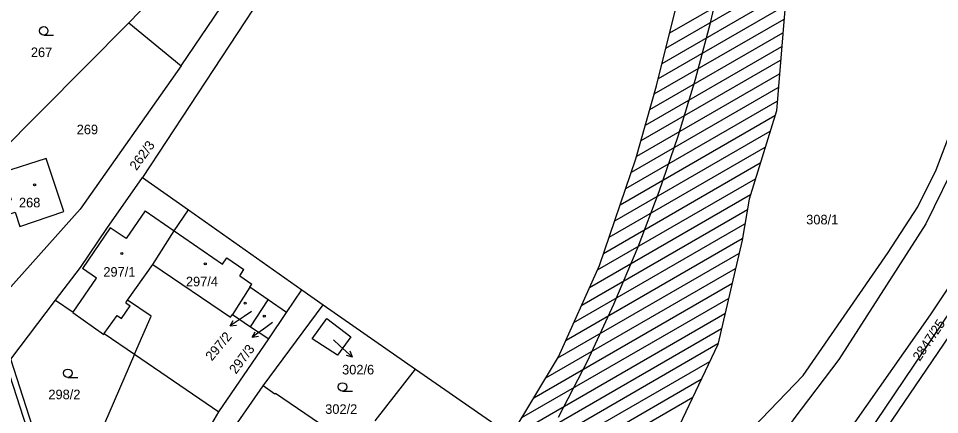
# Model space of a CAD drawing. Extents: x -558500 to -557517, y -1073973 to -1073051.
# Drawn here: x -558169.6 to -558006.2, y -1073303.2 to -1073232.9 of the extents above; entities that cross this region are included whole.
import ezdxf

# ---------------------------------------------------------------- set-up
doc = ezdxf.new("R2010")
doc.units = 0
for name, color, linetype in [('Hranice parcel', 7, 'Continuous'), ('Kolej', 7, 'Continuous'), ('Parcelní čísla', 7, 'Continuous'), ('Pop  PČ popisy', 7, 'Continuous'), ('Svazek obcí údolí Desné', 7, 'Continuous'), ('Vnitřní kresba', 7, 'Continuous'), ('Značky budov', 7, 'Continuous'), ('Značky kultur', 7, 'Continuous')]:
    doc.layers.add(name, color=color, linetype=linetype)

msp = doc.modelspace()

# ---------------------------------------------------------------- linework, layer by layer
at = {"layer": 'Hranice parcel'}
for p, q in [((-558140.75, -1073241.36), (-558126.3, -1073220.06)), ((-558122.4, -1073222.85), (-558147.61, -1073261.18)), ((-558180.27, -1073264.19), (-558150.02, -1073233.76)), ((-558150.02, -1073233.76), (-558140.75, -1073241.36)), ((-558147.61, -1073261.18), (-558139.47, -1073266.91)), ((-558139.47, -1073266.91), (-558119.31, -1073281.1)), ((-557994.86, -1073270.9), (-558022.09, -1073311.21)), ((-558122.04, -1073285.13), (-558119.31, -1073281.1)), ((-558119.31, -1073281.1), (-558115.55, -1073283.75)), ((-558170.97, -1073293.42), (-558163.02, -1073282.94)), ((-558128.43, -1073287.66), (-558125.31, -1073282.88)), ((-558122.04, -1073285.13), (-558125.31, -1073282.88)), ((-558126.22, -1073298.15), (-558115.55, -1073283.75)), ((-558125.21, -1073289.82), (-558122.04, -1073285.13)), ((-558115.55, -1073283.75), (-558099.14, -1073295.15)), ((-558128.43, -1073287.66), (-558125.21, -1073289.82)), ((-558134.04, -1073302.76), (-558125.21, -1073289.82)), ((-558161.8, -1073321.91), (-558170.97, -1073293.42)), ((-558149, -1073292.52), (-558161.8, -1073321.91)), ((-558149, -1073292.52), (-558134.04, -1073302.76)), ((-558106.35, -1073304.33), (-558099.14, -1073295.15)), ((-558099.14, -1073295.15), (-558082.18, -1073306.93)), ((-558156.12, -1073339.58), (-558134.04, -1073302.76))]:
    msp.add_line(p, q, dxfattribs=at)
for points in [[(-557998.11, -1073217.81), (-557996.7, -1073222.28), (-557998.38, -1073242.39), (-558002.78, -1073257.43), (-558008.62, -1073269.37), (-558024.06, -1073293.44), (-558032.02, -1073303.96), (-558033.31, -1073305.78)], [(-558142.95, -1073224.45), (-558142.49, -1073225.95), (-558150.02, -1073233.76)], [(-558140.75, -1073241.36), (-558158.68, -1073266.81), (-558173.01, -1073282.83), (-558173.98, -1073283.88)], [(-558179.28, -1073267.3), (-558171.41, -1073263.5), (-558170.89, -1073265.11), (-558172.23, -1073265.52), (-558171.5, -1073267.74), (-558170.17, -1073267.35), (-558169.36, -1073269.84), (-558161.57, -1073267.22), (-558164.69, -1073257.79), (-558172.45, -1073260.31), (-558172.35, -1073260.6), (-558180.27, -1073264.19)], [(-558163.02, -1073282.94), (-558158.61, -1073277.12), (-558153.96, -1073270.21), (-558147.61, -1073261.18)], [(-558149, -1073292.52), (-558146.08, -1073285.8), (-558150.24, -1073282.94), (-558145.79, -1073276.6), (-558141.97, -1073270.62), (-558139.47, -1073266.91)], [(-558021.55, -1073305.19), (-558007.79, -1073285.56), (-557998.91, -1073272.25), (-557998.29, -1073271.45), (-557997.41, -1073270.82), (-557995.96, -1073270.7)], [(-557992.18, -1073271.14), (-558017.7, -1073308.66), (-558015.75, -1073309.85), (-558004.08, -1073317.8), (-557996.67, -1073322.48), (-557993.43, -1073325.31), (-557988.49, -1073331.84)], [(-558125.31, -1073282.88), (-558128.57, -1073280.64), (-558131.66, -1073285.5), (-558128.43, -1073287.66)], [(-558163.02, -1073282.94), (-558159.92, -1073285.05), (-558159.98, -1073285.15), (-558154.48, -1073289), (-558154.38, -1073288.84), (-558149, -1073292.52)], [(-558114.88, -1073286.21), (-558110.67, -1073289.41), (-558112.99, -1073292.67), (-558117.52, -1073289.79), (-558114.88, -1073286.21)], [(-558140.29, -1073392.34), (-558154.66, -1073347.35), (-558171.71, -1073294.39)], [(-558134.81, -1073315.38), (-558130.55, -1073309.06), (-558132.76, -1073307.6), (-558126.22, -1073298.15)], [(-558113.61, -1073306.59), (-558124.02, -1073299.5), (-558124.12, -1073299.64), (-558126.22, -1073298.15)]]:
    msp.add_lwpolyline(points, dxfattribs=at)
at = {"layer": 'Kolej'}
msp.add_lwpolyline([(-558073.77, -1073303.7), (-558068.68, -1073293.77), (-558063.96, -1073283.66), (-558059.66, -1073273.45), (-558055.92, -1073263.64), (-558052.59, -1073253.84), (-558049.52, -1073243.71), (-558046.86, -1073233.73), (-558044.36, -1073223.02)], dxfattribs=at)
at = {"layer": 'Pop  PČ popisy'}
for p, q in [((-558128.29, -1073284.96), (-558129.56, -1073285.83)), ((-558129.56, -1073285.83), (-558132.05, -1073287.51)), ((-558132.05, -1073287.51), (-558131.5, -1073286.53)), ((-558124.56, -1073286.91), (-558125.73, -1073287.76)), ((-558132.05, -1073287.51), (-558130.94, -1073287.36)), ((-558125.73, -1073287.76), (-558128.16, -1073289.52)), ((-558128.16, -1073289.52), (-558127.64, -1073288.53)), ((-558128.16, -1073289.52), (-558127.05, -1073289.34)), ((-558113.72, -1073290), (-558112.59, -1073291.03)), ((-558112.59, -1073291.03), (-558110.36, -1073293.04)), ((-558110.36, -1073293.04), (-558111.44, -1073292.74)), ((-558110.36, -1073293.04), (-558110.77, -1073292))]:
    msp.add_line(p, q, dxfattribs=at)
at = {"layer": 'Svazek obcí údolí Desné'}
for p, q in [((-558054.07, -1073235.53), (-558032.98, -1073223.36)), ((-558054.74, -1073238.23), (-558033.19, -1073225.78)), ((-558055.41, -1073240.93), (-558033.39, -1073228.21)), ((-558056.08, -1073243.62), (-558033.59, -1073230.64)), ((-558056.81, -1073246.35), (-558033.79, -1073233.06)), ((-558057.59, -1073249.11), (-558034, -1073235.49)), ((-558058.37, -1073251.87), (-558034.2, -1073237.92)), ((-558059.14, -1073254.63), (-558034.4, -1073240.34)), ((-558059.92, -1073257.38), (-558034.6, -1073242.77)), ((-558060.87, -1073260.24), (-558034.81, -1073245.19)), ((-558061.86, -1073263.12), (-558035.01, -1073247.62)), ((-558062.84, -1073266), (-558035.4, -1073250.16)), ((-558063.83, -1073268.88), (-558036.27, -1073252.97)), ((-558064.82, -1073271.76), (-558037.13, -1073255.77)), ((-558065.8, -1073274.64), (-558037.99, -1073258.58)), ((-558066.9, -1073277.58), (-558038.86, -1073261.39)), ((-558068.29, -1073280.69), (-558039.72, -1073264.2)), ((-558069.68, -1073283.8), (-558040.29, -1073266.84)), ((-558071.07, -1073286.91), (-558040.74, -1073269.4)), ((-558072.46, -1073290.03), (-558041.19, -1073271.97)), ((-558073.89, -1073293.16), (-558041.79, -1073274.63)), ((-558076.02, -1073296.7), (-558042.41, -1073277.3)), ((-558078.15, -1073300.24), (-558043.03, -1073279.97)), ((-558080.29, -1073303.78), (-558043.65, -1073282.63)), ((-558082.4, -1073307.31), (-558044.27, -1073285.3)), ((-558084.38, -1073310.76), (-558044.89, -1073287.97)), ((-558086.37, -1073314.22), (-558045.51, -1073290.64)), ((-558089.02, -1073318.06), (-558046.97, -1073293.79)), ((-558091.87, -1073322.02), (-558048.48, -1073296.97)), ((-558069.24, -1073311.26), (-558049.99, -1073300.15))]:
    msp.add_line(p, q, dxfattribs=at)
for points in [[(-558082.18, -1073306.93), (-558073.77, -1073292.96), (-558066.53, -1073276.76), (-558060.05, -1073257.85), (-558056.4, -1073244.89), (-558045.6, -1073201.5), (-558043.14, -1073189.96)], [(-558025.67, -1073189.86), (-558032.09, -1073212.63), (-558035.15, -1073249.33), (-558039.97, -1073265.01), (-558041.24, -1073272.26), (-558045.55, -1073290.79), (-558055.77, -1073312.33), (-558066.64, -1073329.29), (-558067.37, -1073328.67), (-558071.91, -1073335.47), (-558071.45, -1073339.78), (-558072.38, -1073341.74), (-558078.52, -1073350.81)], [(-558066.74, -1073350.64), (-558065.9, -1073348.86), (-558061.08, -1073328.44), (-558060.65, -1073327.54), (-558046.7, -1073313.29), (-558030.4, -1073296.27), (-558015.33, -1073274.48), (-558010.02, -1073266.4), (-558006.82, -1073259.79), (-558003.58, -1073251.39), (-558001.93, -1073245.63), (-558000.3, -1073233.47), (-558000.14, -1073230.76), (-558000.21, -1073228.76), (-558000.67, -1073225.31), (-558001.93, -1073222.03), (-558003.18, -1073219.55), (-558003.41, -1073218.32), (-558003.28, -1073217.31), (-558002.8, -1073216.38), (-558000.9, -1073214.81), (-557999.34, -1073213.91), (-558005.3, -1073194.99), (-558007.3, -1073189.81)]]:
    msp.add_lwpolyline(points, dxfattribs=at)
at = {"layer": 'Vnitřní kresba'}
for p, q in [((-558147.14, -1073267.06), (-558141.97, -1073270.62)), ((-558141.97, -1073270.62), (-558133.4, -1073276.52)), ((-558133.4, -1073276.52), (-558132.65, -1073275.44)), ((-558132.65, -1073275.44), (-558129.62, -1073277.52)), ((-558145.79, -1073276.6), (-558132.02, -1073285.94)), ((-558130.36, -1073278.61), (-558129.62, -1073277.52)), ((-558130.36, -1073278.61), (-558128.2, -1073280.1)), ((-558128.57, -1073280.64), (-558128.2, -1073280.1)), ((-558150.56, -1073283.39), (-558150.24, -1073282.94)), ((-558150.56, -1073283.39), (-558149.78, -1073283.94)), ((-558151.33, -1073286.18), (-558149.78, -1073283.94)), ((-558154.38, -1073288.84), (-558152.12, -1073285.63)), ((-558152.12, -1073285.63), (-558151.33, -1073286.18)), ((-558132.02, -1073285.94), (-558131.66, -1073285.5))]:
    msp.add_line(p, q, dxfattribs=at)
for points in [[(-558147.14, -1073267.06), (-558150.53, -1073272.01), (-558153.32, -1073270.09), (-558158.27, -1073277.3)], [(-558159.92, -1073285.05), (-558155.77, -1073279.02), (-558158.27, -1073277.3)]]:
    msp.add_lwpolyline(points, dxfattribs=at)
at = {"layer": 'Značky budov'}
for centre in [(-558166.74, -1073262.46), (-558151.26, -1073274.64), (-558136.46, -1073276.5), (-558129.37, -1073283.49), (-558125.99, -1073285.78)]:
    msp.add_circle(centre, 0.175, dxfattribs=at)
at = {"layer": 'Značky kultur'}
for p, q in [((-558165.13, -1073235.9), (-558163.38, -1073235.9)), ((-558160.84, -1073296.66), (-558159.09, -1073296.66)), ((-558112.12, -1073299.08), (-558110.37, -1073299.08))]:
    msp.add_line(p, q, dxfattribs=at)
for centre in [(-558165.13, -1073235.15), (-558160.84, -1073295.91), (-558112.12, -1073298.33)]:
    msp.add_circle(centre, 0.75, dxfattribs=at)

# ---------------------------------------------------------------- texts
at = {"layer": 'Parcelní čísla'}
for s, p in [('267', (-558167.41, -1073239.81)), ('269', (-558159.28, -1073253.5)), ('268', (-558169.52, -1073266.47)), ('308/1', (-558029.85, -1073269.49)), ('297/1', (-558154.55, -1073278.77)), ('297/4', (-558139.9, -1073280.48)), ('302/6', (-558112.19, -1073296.11)), ('298/2', (-558164.3, -1073300.51)), ('302/2', (-558115.19, -1073303.11))]:
    msp.add_text(s, height=1.7, dxfattribs=at).set_placement(p)
for s, rotation, p in [('262/3', 54, (-558148.67, -1073260.04)), ('2847/25', 56, (-558009.7, -1073293.88)), ('297/2', 50, (-558135.3, -1073293.83)), ('297/3', 53, (-558131.02, -1073296.16))]:
    msp.add_text(s, height=1.7, rotation=rotation, dxfattribs=at).set_placement(p)

doc.saveas('drawing.dxf')
